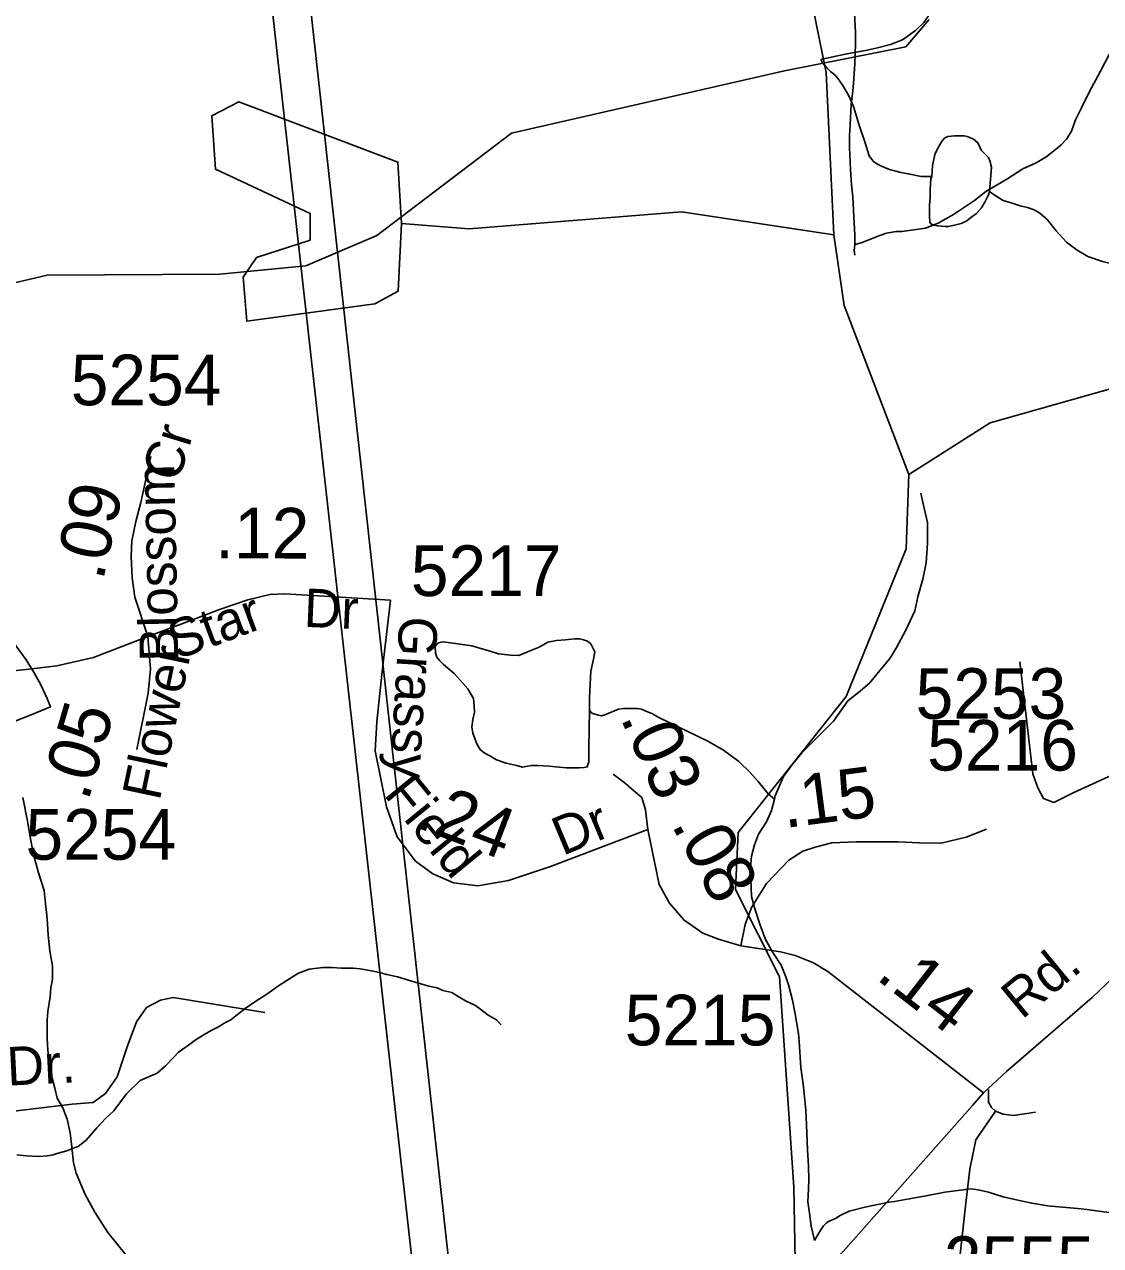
# Model space of a CAD drawing. Extents: x 2169602 to 2449496, y 721995 to 810662.
# Drawn here: x 2388195 to 2390850, y 788453 to 791467 of the extents above; entities that cross this region are included whole.
import ezdxf

# ---------------------------------------------------------------- set-up
doc = ezdxf.new("R2010")
doc.units = 0
doc.layers.add('Default', color=7, linetype='Continuous')

msp = doc.modelspace()

# ---------------------------------------------------------------- linework, layer by layer
at = {"layer": 'Default'}
for points in [[(2388532, 794512), (2388524.3, 794386.7), (2388523.1, 794327.2), (2388520.7, 794229), (2388523.1, 794139.1), (2388525.5, 794016.6), (2389605.5, 784350.2), (2389578.3, 783610.7), (2382980.8, 774642.5), (2382114, 772097)], [(2388625.4, 794491.7), (2388616.4, 794288.1), (2388616.4, 794167), (2388617.8, 794076.8), (2389691.7, 784332), (2389662.7, 783599.5), (2383058, 774616.8), (2382114, 771837.6)], [(2390192, 790947.3), (2390173.1, 791347.9), (2390071, 791848.6), (2389894, 792347.6), (2389575, 792967.8)], [(2390706.3, 791982.8), (2390672.7, 791942.4), (2390654.7, 791912.3), (2390627.2, 791870.2), (2390611.4, 791834), (2390597.5, 791791.9), (2390558.1, 791718), (2390525.9, 791658), (2390504.4, 791619.8), (2390484.7, 791583.5), (2390472.4, 791561.4), (2390463.1, 791543.3), (2390448.8, 791521.5), (2390433.2, 791499.1), (2390413.7, 791471.3), (2390393.4, 791451.3), (2390361.6, 791428.9), (2390331.5, 791416.8), (2390299.5, 791408.7), (2390269.6, 791402.6), (2390224.1, 791394.1), (2390177.7, 791384.1), (2390160.1, 791379.9)], [(2388676.5, 790850), (2388889.2, 790870.9), (2389064.3, 790946), (2389396.3, 791198.4), (2390070.3, 791351.9), (2390369.2, 791411.4), (2390427.3, 791479.2)], [(2390243, 791494.8), (2390245.3, 791447.1), (2390245.3, 791419.1), (2390243.9, 791369), (2390240, 791320.9), (2390238.3, 791302.9), (2390234.4, 791269), (2390232.4, 791219), (2390230.5, 791192.9), (2390230.7, 791162.9), (2390232.8, 791109), (2390235, 791071), (2390238.9, 791041.2), (2390241.2, 790990.9), (2390243.7, 790947.1), (2390243.9, 790923.2)], [(2390881.2, 791411.7), (2390849.6, 791351.6), (2390821.7, 791299.4), (2390801.8, 791259.4), (2390788.3, 791231.5), (2390778, 791203.4), (2390766.1, 791183.3), (2390752.4, 791169.2), (2390742.5, 791161.3), (2390714.7, 791139.2), (2390690.7, 791125), (2390658.5, 791110.7), (2390618.9, 791084.7), (2390567, 791054.4), (2390538.7, 791032.3), (2390509, 791012.1), (2390487.1, 790997.9), (2390449.5, 790976.1), (2390417.7, 790963.8), (2390389.4, 790959.6), (2390359.3, 790955.6), (2390345.8, 790955.7), (2390321.8, 790951.6), (2390305.4, 790945.5), (2390259.4, 790927.3), (2390243.9, 790923.2)], [(2390433.2, 791091.5), (2390407.4, 791091.3), (2390379.5, 791097.2), (2390357.5, 791100.9), (2390329.4, 791108.8), (2390309.1, 791116.8), (2390297.5, 791122.6), (2390289.5, 791128.7), (2390283.1, 791136.5), (2390279, 791142.4), (2390269, 791174.3), (2390254.6, 791218.3), (2390240.7, 791264.2), (2390228.4, 791290.4), (2390214, 791316.1), (2390202.3, 791332.1), (2390194.1, 791341.9), (2390184.3, 791349.8), (2390174.2, 791359.9), (2390163.8, 791372), (2390160.1, 791379.9)], [(2389125.1, 790975.7), (2389117.1, 790808.6), (2389059.1, 790777), (2388743.1, 790734.2), (2388734.1, 790842.6), (2388767.1, 790891.2), (2388899.9, 790934.4), (2388899.9, 791000), (2388666, 791109.8), (2388657, 791241.1), (2388724, 791275.9), (2389116.1, 791126.8), (2389125.1, 790975.7)], [(2390575.7, 791054.1), (2390579.4, 791094.1), (2390581, 791114.2), (2390579.2, 791120.1), (2390577.2, 791128.2), (2390573.3, 791138.1), (2390565.3, 791146.1), (2390555, 791156.2), (2390553, 791162.2), (2390547, 791174.1), (2390540.7, 791179.9), (2390534.9, 791184), (2390521, 791189.8), (2390513, 791191.8), (2390498.8, 791191.9), (2390489.2, 791191.8), (2390473, 791189.7), (2390465.2, 791185.7), (2390459, 791179.7), (2390449, 791163.3), (2390441, 791145.5), (2390435, 791117.6), (2390433.2, 791091.5)], [(2390433.2, 791091.5), (2390431.4, 791085.3), (2390429.7, 791057.6), (2390429.7, 791039.3), (2390428.1, 791021.3), (2390427.9, 791005.5), (2390428.1, 790993.3), (2390428.3, 790979.5), (2390430.1, 790975.5), (2390434, 790973.3), (2390437.9, 790971.5), (2390448.2, 790969.5), (2390466.2, 790967.7), (2390474.2, 790967.7), (2390482.2, 790969.7), (2390492.5, 790971.8), (2390506.2, 790975.8), (2390519.9, 790981.9), (2390529.8, 790990.1), (2390543.9, 791000.2), (2390556, 791014.1), (2390565.5, 791030.1), (2390573.7, 791046.3), (2390575.7, 791054.1)], [(2391052.7, 790846.9), (2391048.8, 790847.1), (2391030.5, 790845), (2391014.9, 790842.9), (2390994.8, 790846.8), (2390970.6, 790852.4), (2390938.9, 790860.5), (2390914.7, 790866.2), (2390910.6, 790866.4), (2390890.7, 790872.3), (2390854.4, 790881.8), (2390818.5, 790893.7), (2390792.2, 790909.4), (2390766.2, 790929.6), (2390740.4, 790957), (2390717.8, 790985.2), (2390700, 791000.9), (2390686, 791009.1), (2390669.6, 791014.8), (2390651.6, 791018.7), (2390629.4, 791026.6), (2390609.5, 791032.4), (2390589.5, 791044.3), (2390575.7, 791054.1)], [(2390192, 790947.3), (2389816.1, 791004.2), (2389292, 790962.5), (2389125.1, 790975.7)], [(2390376.9, 790356.3), (2390217, 790773), (2390192, 790947.3)], [(2390243.9, 790923.2), (2390242, 790908.9), (2390243.9, 790897.2)], [(2387361.1, 790469.2), (2387561.2, 790596.3), (2387919.3, 790697.2), (2388110.2, 790814.6), (2388251.2, 790847.9), (2388676.5, 790850)], [(2390376.9, 790356.3), (2390577.1, 790483.5), (2390935.1, 790584.4), (2391126, 790701.8), (2391267.1, 790735), (2391692.3, 790737.2)], [(2388506.3, 790400.1), (2388481.7, 790286.9), (2388470, 790240.1), (2388460.1, 790192.1), (2388457.7, 790154), (2388460.8, 790101.1), (2388467.5, 790053.1), (2388499.3, 789956.2)], [(2387495, 785885), (2387680.9, 785956.6), (2388205, 786024.6), (2388587.9, 786033.2), (2388805, 786078), (2388920.9, 786160.9), (2389011.9, 786346.1), (2389544, 786604.1), (2389725.9, 786872.7), (2389824.9, 787090.5), (2390106.9, 787383.2), (2390155.9, 787533.1), (2390155.1, 787815.2), (2390105, 787957.3), (2390092.9, 788597.2), (2390058.1, 789116.3), (2389949, 789331.8), (2389956, 789472.7), (2390221.9, 789808.4), (2390370, 790172.8), (2390376.9, 790356.3)], [(2390406.1, 790310.1), (2390412.4, 790284), (2390422.7, 790237.8), (2390422.7, 790215.9), (2390422.5, 790186.3), (2390419.2, 790138.2), (2390411.2, 790098), (2390399.1, 790053.9), (2390391.3, 790019.8), (2390369.8, 789972), (2390345.8, 789927.8), (2390330, 789901.7), (2390298.2, 789863.6), (2390280.2, 789841.6), (2390256.8, 789821.6), (2390226.4, 789797.4), (2390190.8, 789747.2), (2390151, 789707), (2390113.2, 789668.9), (2390089.5, 789640.9), (2390067.3, 789610.9), (2390047.4, 789562.8), (2390045.8, 789554.5)], [(2389097.7, 790046), (2388837.6, 790061.6), (2388800.5, 790060.1), (2388745.6, 790046.7), (2388675.9, 790023), (2388603.2, 789994.8), (2388499.3, 789956.2)], [(2389732.9, 789479.7), (2389492.5, 789388.9), (2389389, 789354), (2389313.1, 789340.9), (2389253.5, 789348.2), (2389202.7, 789370.7), (2389159.8, 789402), (2389114.1, 789461.6), (2389087.9, 789535.7), (2389059.9, 789674.5), (2389064.1, 789746), (2389076.7, 789862.3), (2389097.7, 790046)], [(2387892.1, 789843.3), (2388199.1, 789874.6), (2388274.7, 789883.9), (2388365.4, 789904.2), (2388499.3, 789956.2)], [(2388169.3, 789746.3), (2388211.2, 789762.7), (2388245, 789776.7), (2388259.2, 789783), (2388251.2, 789802.9), (2388235, 789836.6), (2388218.8, 789866.6), (2388198.7, 789898.5), (2388170.4, 789938.4)], [(2388499.3, 789956.2), (2388506, 789875.9), (2388499.8, 789816.8), (2388472.4, 789677.6)], [(2389588.9, 789774.6), (2389587.3, 789680.7), (2389587.3, 789660.4), (2389587.1, 789646.7), (2389583.4, 789634.6), (2389575.4, 789632.6), (2389563.5, 789632.4), (2389531.7, 789632.3), (2389489.5, 789636.3), (2389461.6, 789638), (2389445.4, 789638), (2389423.7, 789634), (2389409.3, 789637.8), (2389383.5, 789643.8), (2389359.5, 789651.9), (2389343.1, 789661.6), (2389329.1, 789669.4), (2389319.5, 789677.4), (2389311.1, 789691.3), (2389301.4, 789717.4), (2389299, 789733.2), (2389301, 789751.2), (2389304.9, 789769.2), (2389304.7, 789785.5), (2389302.7, 789803.3), (2389288.7, 789827.3), (2389276.6, 789841.2), (2389254.7, 789864.9), (2389228.6, 789887.1), (2389218.8, 789897.1), (2389212.4, 789904.9), (2389208.6, 789914.9), (2389208.3, 789931.1), (2389210.2, 789934.9), (2389216.3, 789940.9), (2389228, 789943.1), (2389258, 789939), (2389298.4, 789933.3), (2389326.3, 789925.4), (2389346.1, 789919.6), (2389364.4, 789913.6), (2389394.3, 789909.8), (2389414.2, 789909.7), (2389444.4, 789921.8), (2389464.5, 789930.1), (2389486, 789942.2), (2389507.9, 789946.2), (2389529.9, 789948.2), (2389552, 789950.5), (2389564.1, 789950.3), (2389574.2, 789948.4), (2389584, 789944.4), (2389592, 789938.4), (2389602.3, 789918.6), (2389598.4, 789900.5), (2389592.6, 789870.5), (2389590.6, 789838.4), (2389588.9, 789804.6), (2389588.9, 789774.6)], [(2391219.4, 789470.3), (2391116, 789520.1), (2390976.7, 789583.2), (2390929.4, 789614.8), (2390879.5, 789614.8), (2390782.2, 789570.1), (2390734.9, 789546.4), (2390708.7, 789556.9), (2390695.5, 789583.2), (2390682.4, 789617.4), (2390650.8, 789893.5)], [(2390045.8, 789554.5), (2390029.8, 789568.3), (2390005.4, 789598.4), (2389985.3, 789620.5), (2389957.2, 789648.2), (2389919.3, 789675.9), (2389880.9, 789697.9), (2389831.3, 789721.7), (2389786.8, 789743.4), (2389758.7, 789757.4), (2389744.6, 789765.2), (2389730.8, 789771.3), (2389716.9, 789777.1), (2389707, 789779), (2389688.6, 789778.9), (2389673, 789778.9), (2389660.7, 789777.1), (2389650.6, 789772.9), (2389636.5, 789767), (2389626.9, 789762.7), (2389618.5, 789760.8), (2389608.6, 789762.7), (2389596.5, 789766.5), (2389593, 789768.7), (2389588.9, 789774.6)], [(2391429.3, 789691.8), (2391002.8, 789230.5), (2390829.1, 789065.1), (2390617.7, 788882.9), (2390561, 788830)], [(2389732.9, 789479.7), (2389727.1, 789528.4), (2389717.7, 789558.9), (2389697.7, 789576.4), (2389678.1, 789593.8), (2389647.6, 789616.3)], [(2388190.5, 789558.6), (2388202.4, 789500.8), (2388210.6, 789452.9), (2388216.9, 789418.7), (2388229.2, 789373), (2388243.2, 789329.1), (2388247.1, 789296.9), (2388249.7, 789268.9), (2388251.6, 789247.1), (2388253.2, 789218.9), (2388257.5, 789180.9), (2388264.1, 789143), (2388263.9, 789117.1), (2388264.1, 789111), (2388260, 789088.9), (2388258.1, 789067.2), (2388252.6, 789031.2), (2388250.5, 789009.1), (2388251, 788964.9), (2388252.8, 788935), (2388259, 788883), (2388269.4, 788841.3), (2388275.2, 788817.2), (2388289.5, 788793.2), (2388299.8, 788765.3), (2388307.6, 788731.2), (2388311.7, 788697.3), (2388316.2, 788657.3), (2388322.5, 788631.6), (2388344.5, 788579.6), (2388368.5, 788535.8), (2388400.6, 788485.9), (2388444.9, 788430.1)], [(2390045.8, 789554.5), (2390037.6, 789526.6), (2390025.7, 789498.8), (2390005.8, 789468.5), (2389996, 789442.4), (2389988.4, 789414.4), (2389986.3, 789386.3), (2389986.7, 789358.2), (2389988.8, 789314.5), (2389997, 789284.5), (2390009.3, 789246.5), (2390023, 789208.8), (2390041.5, 789176.8), (2390061.6, 789144.9), (2390073.5, 789116.7), (2390079.6, 789096.8), (2390089.9, 789059.1), (2390095.8, 789029), (2390104.2, 788977), (2390106.5, 788957.2), (2390110.6, 788892.9), (2390116.7, 788845.3), (2390123.1, 788787.2), (2390124.7, 788751.2), (2390127.2, 788689.2), (2390129.4, 788649.1), (2390129.9, 788615.4), (2390129.6, 788593.5), (2390128, 788561.3), (2390131.9, 788533.5), (2390136.2, 788501.2), (2390142.4, 788473.6), (2390144.4, 788465.5)], [(2389962.5, 789192.7), (2389907.3, 789209), (2389868.8, 789224.6), (2389822.3, 789255.9), (2389786.7, 789298), (2389760.5, 789344.5), (2389732.9, 789479.7)], [(2389962.5, 789192.7), (2389973, 789245.7), (2389989, 789287.9), (2390025.3, 789346.7), (2390080.9, 789404.1), (2390115.7, 789426.7), (2390145.5, 789436.8), (2390186.9, 789447), (2390246.5, 789449.9), (2390350.3, 789449.2), (2390402.6, 789447), (2390456.7, 789446.3), (2390518.5, 789460.8), (2390568.6, 789481.2)], [(2390561, 788830), (2390177.1, 789129.4), (2390141.5, 789151.2), (2390096.5, 789168.7), (2390060.2, 789177.8), (2389962.5, 789192.7)], [(2389371.4, 788998), (2389359.3, 789010), (2389339.3, 789022), (2389321.2, 789035.7), (2389307.3, 789045.9), (2389283.3, 789057.6), (2389269.1, 789065.4), (2389249, 789077.4), (2389227.1, 789083.1), (2389212.9, 789089.3), (2389192.6, 789093.2), (2389172.7, 789099.1), (2389144.9, 789107), (2389114.9, 789116.7), (2389088.7, 789122.3), (2389072.9, 789126.3), (2389054.8, 789130.3), (2389023.1, 789135.9), (2389006.7, 789138), (2388976.9, 789138), (2388953.1, 789139.6), (2388931, 789139.7), (2388897.2, 789135.5), (2388870.7, 789125.3), (2388844.7, 789109.3), (2388819, 789092.9), (2388795.2, 789075), (2388763.5, 789054.7), (2388739.5, 789038.5), (2388703.8, 789010.2), (2388687.4, 789002.1)], [(2388787.7, 789028.2), (2388561.5, 789065.2), (2388530.7, 789059.1), (2388495.7, 789040.5), (2388471, 789005.6), (2388448.4, 788943.8), (2388423.8, 788869.8), (2388395, 788828.6), (2388364.1, 788806), (2388312.7, 788801.9), (2387605.4, 788717.5), (2387353.7, 788663.7)], [(2388687.4, 789002.1), (2388675.5, 788994.2), (2388655.6, 788984.2), (2388635.7, 788972.2), (2388615.8, 788959.8), (2388599.8, 788947.6), (2388585.7, 788937.6), (2388573.8, 788929.6), (2388564.6, 788919.3), (2388542.4, 788897.1), (2388522.5, 788879), (2388480.7, 788860.6), (2388446.9, 788828), (2388415.1, 788785.7), (2388395.2, 788767.6), (2388373.3, 788743.8), (2388347.4, 788713.6), (2388327.7, 788697.5), (2388319.7, 788695.5), (2388299.6, 788687.2), (2388277.9, 788681.2), (2388265.6, 788676.9), (2388251.9, 788675), (2388229.7, 788673), (2388199.4, 788674.8), (2388175.6, 788676.8)], [(2390561, 788830), (2390534, 788799.1), (2390214.8, 788438.9), (2389875.8, 788093.4), (2389391.3, 787607.5), (2389236.5, 787442), (2389123.4, 787301.7), (2388741.5, 786750.9), (2388611.8, 786604.3), (2388456.9, 786476.6), (2388314.6, 786376.1), (2388072.9, 786258.8), (2387639.7, 786066.1), (2387466, 785982.4), (2387311.1, 785881.8), (2387054.7, 785722.7)], [(2390573.1, 788838.3), (2390573.8, 788807.1), (2390580.7, 788794.1), (2390590.7, 788785.2)], [(2390590.7, 788785.2), (2390541.9, 788714.5), (2390527.2, 788641.7), (2390517.7, 788557.7), (2390443.2, 787892.3), (2390461.6, 787842.4), (2390451.1, 787716.2)], [(2390590.7, 788785.2), (2390609.6, 788777.2), (2390634.4, 788774.2), (2390668.2, 788779.2), (2390689.1, 788782.2)], [(2390869.9, 788534.7), (2390816, 788542.4), (2390801.8, 788544.1), (2390719.8, 788551.7), (2390680, 788557.7), (2390646, 788565.3), (2390609.9, 788573.2), (2390573.6, 788585.2), (2390547.7, 788591.1), (2390529.9, 788593), (2390497.7, 788588.9), (2390465.5, 788584.8), (2390423.9, 788576.6), (2390378, 788568.5), (2390341.5, 788562.2), (2390327.5, 788560.3), (2390268.3, 788547.8), (2390229.9, 788537.8), (2390207.8, 788527.7), (2390195.9, 788519.8), (2390180.1, 788513.7), (2390173.9, 788509.7), (2390166.1, 788501.6), (2390158.1, 788489.4), (2390144.4, 788465.5)]]:
    msp.add_lwpolyline(points, dxfattribs=at)

# ---------------------------------------------------------------- texts
for s, p in [('5254', (2388309, 790526.9)), ('5217', (2389148.1, 790056.1)), ('5253', (2390393.5, 789753.1)), ('5216', (2390422.1, 789625.5)), ('5254', (2388197.3, 789405.4)), ('5215', (2389675.9, 788947.3)), ('2555', (2390463.3, 788351.1))]:
    msp.add_text(s, height=125, dxfattribs=at).set_placement(p)
for s, height, rotation, p in [('Cr', 95, 72.844, (2388574, 790333.7)), ('Blossom', 95, 91.1762, (2388574.6, 789895.2)), ('.09', 125, 77.42, (2388388.4, 790091.5)), ('.12', 125, 359.8118, (2388665.2, 790149.3)), ('Dr', 95, 357.5186, (2388882.9, 789980.2)), ('Star', 95, 20.3628, (2388570.5, 789898)), ('Grassy', 95, 266.5478, (2389120.5, 790008.2)), ('Flower', 95, 78.0609, (2388528.2, 789548.7)), ('.05', 125, 73.5577, (2388351.7, 789547.4)), ('.03', 125, 293.9484, (2389664.1, 789756.1)), ('.15', 125, 7.4363, (2390070.5, 789483.4)), ('Field', 95, 309.1927, (2389079.1, 789566.2)), ('.24', 125, 339.1074, (2389155.8, 789487.3)), ('Dr', 95, 22.546, (2389522.4, 789414.3)), ('.08', 125, 298.5946, (2389789.6, 789492)), ('Rd.', 95, 39.4561, (2390655.6, 789009.5)), ('.14', 125, 322.0642, (2390293, 789112.8)), ('Dr.', 95, 2.866, (2388153.6, 788847.9))]:
    msp.add_text(s, height=height, rotation=rotation, dxfattribs=at).set_placement(p)

doc.saveas('drawing.dxf')
